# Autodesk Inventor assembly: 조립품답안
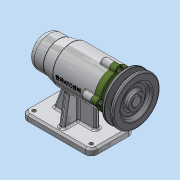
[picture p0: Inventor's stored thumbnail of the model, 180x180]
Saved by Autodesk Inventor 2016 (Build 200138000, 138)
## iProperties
Created: 2019-07
Part Number: 조립품답안
Material: 일반
Document SubType Name: Assembly
Designer: Administrator
Author: Administrator
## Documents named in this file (12)
- C:\Users\Administrator\Desktop\490704V1012\조립품답안.iam
- C:\Users\Administrator\Desktop\490704V1012\본체.ipt
- C:\Users\Administrator\Desktop\490704V1012\커버.ipt
- C:\Users\Administrator\Desktop\490704V1012\베어링 6004.ipt
- C:\Users\Administrator\Desktop\490704V1012\축.ipt
- C:\Users\Administrator\Desktop\490704V1012\볼트 M4.ipt
- C:\Users\Administrator\Desktop\490704V1012\키 5 x 5 x 16.ipt
- C:\Users\Administrator\Desktop\490704V1012\V벨트풀리.ipt
- C:\Users\Administrator\Desktop\490704V1012\멈춤나사 M3.ipt
- C:\Users\Administrator\Desktop\490704V1012\어댑터슬리브.ipt
- C:\Users\Administrator\Desktop\490704V1012\베어링 51202.ipt
- C:\Users\Administrator\Desktop\490704V1012\오일 실.ipt
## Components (1 placed, 1 different names)
1. V벨트풀리:1
